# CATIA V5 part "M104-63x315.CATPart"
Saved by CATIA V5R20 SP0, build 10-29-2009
Part number: M104-63x315
Source: Unknown
Bounding box of the stored display mesh (mm): x -31.459 to 31.459, y -31.459 to 31.459, z 0 to 315
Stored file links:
  C:\Users\Utente\Desktop\IO LAVORO\3D X SITO CF\X SITO\M104\M104-63x315.CATPart
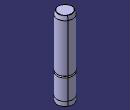
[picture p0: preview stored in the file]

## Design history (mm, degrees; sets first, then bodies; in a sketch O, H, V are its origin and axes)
Body1 (main body)
  Solid1 "PartBody": solid without history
